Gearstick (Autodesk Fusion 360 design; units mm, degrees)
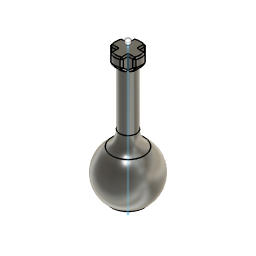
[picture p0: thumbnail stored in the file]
base_feature "Base Feature"
sketch "Sketch1" plane through (0, 0, 0) normal (0, 1, 0) x axis (1, 0, 0)
  line L1 (0, -1.0393) -> (0, 0)
  line L2 (0, -6.5393) -> (0, -1.0393)
  line L3 (7, -13.5223) -> (6, -13.5223)
  line L4 (7, -16.5) -> (7, -13.5223)
  line L5 (9, -16.5) -> (7, -16.5)
  line L6 (9, 0) -> (9, -16.5)
  line L7 (0, 0) -> (9, 0)
  line L8 (1.5, -23.3515) -> (1.5, -13.3515)
  line L9 (3, -2.5393) -> (0, -2.5393)
  line L10 (2.4121, -24.2636) -> (1.5, -23.3515)
  line L11 (2.4121, -27) -> (2.4121, -24.2636)
  line L12 (0, -27) -> (2.4121, -27)
  line L13 (0, 0) -> (0, -27)
  arc A1 centre (0, -6.5393) radius 5.5 clockwise from (0, -1.0393) to (4.4732, -9.7394)
  arc A2 centre (6.6757, -11.05) radius 2.5629 clockwise from (6, -13.5223) to (4.4732, -9.7394)
  arc A3 centre (4.8794, -13.3515) radius 3.3794 clockwise from (1.5, -13.3515) to (2.9115, -10.6041)
  arc A4 centre (0, -6.5393) radius 5 clockwise from (3, -2.5393) to (2.9115, -10.6041)
  point P1 (0, 0)
  point P2 (0, 0)
  point P4 (0, -6.5393)
  point P5 (0, -6.5393)
  point P13 (0, 0)
  point P18 (0, -2.5393)
  point P24 (0, 0)
  point P3 (0, -1.0393)
  point P19 (3, -2.5393)
  point P15 (1.5, -13.3515)
  point P17 (1.5, -23.3515)
  point P8 (6, -13.5223)
  point P9 (7, -13.5223)
  coincident P1 P2
  vertical L1
  parallel L1 L2
  coincident P4 P5
  horizontal L3
  perpendicular L3 L4
  perpendicular L4 L5
  perpendicular L5 L6
  coincident P1 P13
  perpendicular L1 L7
  tangent A3 L8
  coincident L2 P18
  parallel L8 L11
  perpendicular L11 L12
  coincident P1 P24
  perpendicular L7 L13
  tangent A3 A4
  dimension "d1" distance P3 P4 = 5.5
  dimension "d2" distance P18 P19 = 3
  dimension "d4" distance P15 P17 = 10
  dimension "d5" distance L8 L13 = 1.5
  dimension "d6" distance P8 P9 = 1
sketch "Sketch2" plane through (0, 0, 27) normal (0, 0, 1) x axis (-1, 0, 0)
  line L1 (-1.0607, 1.0607) -> (1.0607, 1.0607)
  line L2 (1.0607, -1.0607) -> (1.0607, 1.0607)
  line L3 (-1.0607, -1.0607) -> (1.0607, -1.0607)
  line L4 (-1.0607, 1.0607) -> (-1.0607, -1.0607)
  line L5 (1.0607, 2.1664) -> (1.0607, 1.0607)
  line L6 (-1.0607, 2.4) -> (-1.0607, 1.0607)
  line L7 (1.0607, 2.4) -> (-1.0607, 2.4)
  line L8 (1.0607, 2.1664) -> (1.0607, 2.4)
  line L9 (2.6, 1.0607) -> (1.0607, 1.0607)
  line L10 (2.6, -1.0607) -> (2.6, 1.0607)
  line L11 (1.0607, -1.0607) -> (2.6, -1.0607)
  line L12 (1.0607, -2.5) -> (1.0607, -1.0607)
  line L13 (-1.0607, -2.5) -> (1.0607, -2.5)
  line L14 (-1.0607, -1.0607) -> (-1.0607, -2.5)
  line L15 (-2.9, -1.0607) -> (-1.0607, -1.0607)
  line L16 (-2.9, 1.0607) -> (-2.9, -1.0607)
  line L17 (-1.0607, 1.0607) -> (-2.9, 1.0607)
  line L18 (2.6, 2.4) -> (-2.9, 2.4)
  line L19 (2.6, -2.5) -> (2.6, 2.4)
  line L20 (-2.9, -2.5) -> (2.6, -2.5)
  line L21 (-2.9, 2.4) -> (-2.9, -2.5)
  circle C1 centre (0, 0) radius 2.4121
  circle C2 centre (0, 0) radius 1.5
  point P1 (0, 0)
  point P3 (0, 0)
  point P4 (1.0607, 1.0607)
  point P5 (-1.0607, 1.0607)
  point P6 (1.0607, -1.0607)
  point P7 (-1.0607, -1.0607)
  point P8 (1.0607, 2.1664)
  coincident P1 P3
  coincident C2 P4
  coincident C2 P5
  horizontal L1
  coincident C2 P6
  perpendicular L1 L2
  equal L1 L2
  coincident C2 P7
  perpendicular L2 L3
  coincident C1 P8
  perpendicular L1 L5
  perpendicular L1 L6
  perpendicular L4 L7
  perpendicular L1 L8
  perpendicular L5 L9
  perpendicular L3 L10
  perpendicular L2 L11
  perpendicular L9 L12
  perpendicular L4 L13
  perpendicular L3 L14
  perpendicular L14 L15
  perpendicular L1 L16
  perpendicular L4 L17
  horizontal L18
  vertical L19
  horizontal L20
  vertical L21
  dimension "d7" diameter C2 = 3
revolve "Revolve1" sketch "Sketch1" AlongAngle 360
extrude "Extrude1" cut sketch "Sketch2" profile of C1 L5 L6 L9 L11 L12 L14 L15 L17 against normal blind 5.5
extrude "Extrude2" cut of existing geometry blind -1
chamfer "Chamfer1" distance 0.25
